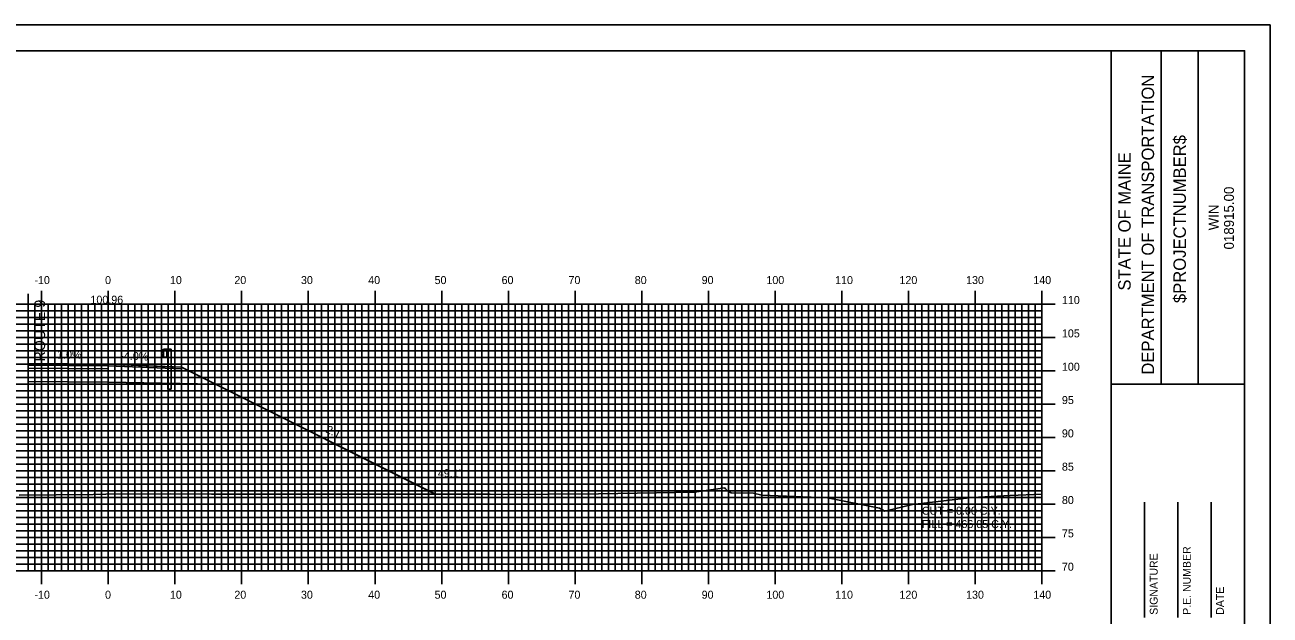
# Model space of a CAD drawing. Extents: x 2846 to 3190, y -1658 to -1438.
# Drawn here: x 2999.7 to 3186.4, y -1526.3 to -1437.7 of the extents above; entities that cross this region are included whole.
import ezdxf

# ---------------------------------------------------------------- set-up
doc = ezdxf.new("R2010")
doc.units = 0
for name, color, linetype in [('ANNOTATION', 7, 'Continuous'), ('BORDER', 7, 'Continuous'), ('D_Guardrail_Beam_Rt', 7, 'Continuous'), ('D_Roadway_Centerline', 7, 'Continuous'), ('D_Roadway_Centerline_Text', 7, 'Continuous'), ('D_Roadway_Edge_Shoulder', 7, 'Continuous'), ('D_Roadway_Edge_TW', 7, 'Continuous'), ('D_Roadway_Pavement', 7, 'Continuous'), ('D_Roadway_SlopeLines', 7, 'Continuous'), ('D_Roadway_SubGrade', 7, 'Continuous'), ('D_Text_Standard', 7, 'Continuous'), ('Default', 7, 'Continuous'), ('H_V ANNOTATION', 7, 'Continuous'), ('MAJOR', 7, 'Continuous'), ('MINOR', 7, 'Continuous'), ('PLOT BOUNDARY', 7, 'Continuous'), ('S_Roadway_Centerline', 7, 'Continuous')]:
    doc.layers.add(name, color=color, linetype=linetype)

msp = doc.modelspace()

# ---------------------------------------------------------------- linework, layer by layer
at = {"layer": 'BORDER'}
for p, q in [((3162.61, -1651.6), (3162.61, -1441.6)), ((3170.07, -1491.61), (3170.07, -1441.61)), ((3175.66, -1491.61), (3175.66, -1441.61)), ((3162.61, -1491.62), (3182.61, -1491.62)), ((3167.61, -1526.6), (3167.61, -1509.3)), ((3172.61, -1526.6), (3172.61, -1509.3)), ((3177.61, -1526.6), (3177.61, -1509.3))]:
    msp.add_line(p, q, dxfattribs=at)
msp.add_lwpolyline([(2862.61, -1651.6), (3182.61, -1651.6), (3182.61, -1441.6), (2862.61, -1441.6)], close=True, dxfattribs=at)
at = {"layer": 'D_Guardrail_Beam_Rt'}
for p, q in [((3020.39, -1486.49), (3020.25, -1486.59)), ((3020.25, -1486.73), (3020.45, -1486.87)), ((3020.45, -1487.06), (3020.25, -1487.2)), ((3020.25, -1487.34), (3020.39, -1487.44)), ((3020.48, -1486.46), (3020.41, -1486.48)), ((3020.41, -1487.45), (3020.48, -1487.46)), ((3020.48, -1486.38), (3021.17, -1486.38)), ((3020.48, -1487.55), (3020.48, -1486.38)), ((3020.48, -1486.93), (3020.48, -1487)), ((3021.17, -1487.55), (3020.48, -1487.55)), ((3021, -1486.38), (3021, -1487.55)), ((3021.11, -1486.38), (3021.11, -1487.55)), ((3021.15, -1492.38), (3021.15, -1487.55)), ((3021.17, -1486.38), (3021.64, -1486.38)), ((3021.17, -1486.38), (3021.17, -1487.55)), ((3021.64, -1486.38), (3021.64, -1492.38)), ((3021.15, -1492.38), (3021.64, -1492.38))]:
    msp.add_line(p, q, dxfattribs=at)
for centre, major_axis, start_param, end_param in [((3020.3, -1486.66), (-0.0877, 0), 5.323254, 7.243116), ((3020.3, -1487.27), (-0.0877, 0), 5.323254, 7.243116), ((3020.42, -1486.52), (-0.0417, 0), 4.907132, 5.323254), ((3020.42, -1487.41), (-0.0417, 0), 0.959931, 1.376053), ((3020.4, -1486.93), (0.0789, 0), 0, 0.959931), ((3020.4, -1487), (0.0789, 0), 5.323254, 6.283185)]:
    msp.add_ellipse(centre, major_axis=major_axis, ratio=0.995501, start_param=start_param, end_param=end_param, dxfattribs=at)
at = {"layer": 'D_Roadway_Centerline'}
msp.add_lwpolyline([(3000.21, -1488.53), (3012.2, -1488.64), (3012.21, -1488.64), (3020.21, -1488.96), (3020.21, -1488.96), (3023.21, -1489.08), (3023.21, -1489.08), (3028.31, -1491.63), (3028.31, -1491.63), (3061.25, -1508.1), (3061.28, -1508.12)], dxfattribs=at)
at = {"layer": 'D_Roadway_Edge_Shoulder'}
for points in [[(3012.21, -1488.64), (3023.21, -1489.08), (3023.21, -1489.33), (3012.21, -1488.89)], [(3012.21, -1488.64), (3020.21, -1488.96), (3020.21, -1488.96), (3023.21, -1489.08), (3023.21, -1489.33), (3012.21, -1488.89)], [(3012.21, -1488.64), (3020.21, -1488.96), (3020.21, -1488.96), (3023.21, -1489.08), (3023.21, -1489.33), (3012.21, -1488.89)], [(3012.21, -1488.64), (3023.21, -1489.08), (3023.21, -1489.33), (3012.21, -1488.89)], [(3012.21, -1488.64), (3023.21, -1489.08), (3023.21, -1489.33), (3012.21, -1488.89)]]:
    msp.add_lwpolyline(points, close=True, dxfattribs=at)
at = {"layer": 'D_Roadway_Edge_TW'}
msp.add_lwpolyline([(3000.21, -1488.53), (3000.21, -1488.78)], dxfattribs=at)
msp.add_lwpolyline([(3000.21, -1488.53), (3000.21, -1488.78)], dxfattribs=at)
msp.add_lwpolyline([(3000.21, -1488.53), (3012.21, -1488.64), (3012.21, -1488.89), (3000.21, -1488.78)], close=True, dxfattribs=at)
msp.add_lwpolyline([(3000.21, -1488.53), (3012.21, -1488.64), (3012.21, -1488.89), (3000.21, -1488.78)], close=True, dxfattribs=at)
msp.add_lwpolyline([(3000.21, -1488.53), (3012.21, -1488.64), (3012.21, -1488.89), (3000.21, -1488.78)], close=True, dxfattribs=at)
at = {"layer": 'D_Roadway_Pavement'}
for points in [[(3000.21, -1488.78), (3000.21, -1489.2)], [(3000.21, -1488.78), (3000.21, -1489.2)], [(3000.21, -1488.78), (3000.21, -1489.2)], [(3000.21, -1488.78), (3000.21, -1489.2)], [(3012.21, -1488.89), (3012.21, -1489.31)], [(3012.21, -1488.89), (3012.21, -1489.31)], [(3012.21, -1488.89), (3012.21, -1489.31)], [(3012.21, -1488.89), (3012.21, -1489.31)], [(3012.21, -1488.89), (3012.21, -1489.31)], [(3012.21, -1488.89), (3012.21, -1489.31)], [(3012.21, -1488.89), (3012.21, -1489.31)], [(3012.21, -1488.89), (3012.21, -1489.31)], [(3012.21, -1488.89), (3012.21, -1489.31)], [(3012.21, -1488.89), (3012.21, -1489.31)], [(3012.21, -1488.89), (3012.21, -1489.31)], [(3012.21, -1488.89), (3012.21, -1489.31)], [(3012.21, -1488.89), (3012.21, -1489.31)], [(3012.21, -1488.89), (3012.21, -1489.31)]]:
    msp.add_lwpolyline(points, dxfattribs=at)
msp.add_lwpolyline([(3000.21, -1488.78), (3012.21, -1488.89), (3012.21, -1489.31), (3000.21, -1489.2)], close=True, dxfattribs=at)
msp.add_lwpolyline([(3000.21, -1488.78), (3012.21, -1488.89), (3012.21, -1489.31), (3000.21, -1489.2)], close=True, dxfattribs=at)
msp.add_lwpolyline([(3000.21, -1488.78), (3012.21, -1488.89), (3012.21, -1489.31), (3000.21, -1489.2)], close=True, dxfattribs=at)
at = {"layer": 'D_Roadway_SlopeLines'}
msp.add_lwpolyline([(3023.21, -1489.08), (3061.28, -1508.12)], dxfattribs=at)
msp.add_lwpolyline([(3023.21, -1489.08), (3061.28, -1508.12)], dxfattribs=at)
msp.add_lwpolyline([(3023.21, -1489.08), (3061.28, -1508.12)], dxfattribs=at)
msp.add_lwpolyline([(3023.21, -1489.08), (3061.28, -1508.12)], dxfattribs=at)
at = {"layer": 'D_Roadway_SubGrade'}
msp.add_line((3000.21, -1478.06), (3000.21, -1491.2), dxfattribs=at)
for points in [[(3000.21, -1489.2), (3012.21, -1489.31), (3012.21, -1491.31), (3000.21, -1491.2)], [(3000.21, -1489.2), (3012.21, -1489.31), (3012.21, -1491.31), (3000.21, -1491.2)], [(3000.21, -1489.2), (3012.21, -1489.31), (3012.21, -1491.31), (3000.21, -1491.2)], [(3012.21, -1489.31), (3012.21, -1488.89), (3023.21, -1489.33), (3023.21, -1489.08), (3028.31, -1491.63), (3012.21, -1491.31)], [(3012.21, -1489.31), (3012.21, -1488.89), (3023.21, -1489.33), (3023.21, -1489.08), (3028.31, -1491.63), (3012.21, -1491.31)], [(3012.21, -1489.31), (3012.21, -1488.89), (3023.21, -1489.33), (3023.21, -1489.08), (3028.31, -1491.63), (3012.21, -1491.31)], [(3012.21, -1489.31), (3012.21, -1488.89), (3023.21, -1489.33), (3023.21, -1489.08), (3028.31, -1491.63), (3012.21, -1491.31)]]:
    msp.add_lwpolyline(points, close=True, dxfattribs=at)
for points in [[(3000.21, -1489.2), (3000.21, -1491.2)], [(3000.21, -1489.2), (3000.21, -1491.2)], [(3028.31, -1491.63), (3012.21, -1491.31), (3012.21, -1489.31), (3012.21, -1488.89), (3023.21, -1489.33)]]:
    msp.add_lwpolyline(points, dxfattribs=at)
at = {"layer": 'Default'}
msp.add_line((3000.21, -1491.2), (3000.21, -1486.87), dxfattribs=at)
at = {"layer": 'MAJOR'}
for p, q in [((3002.21, -1477.6), (3002.21, -1479.6)), ((3012.21, -1477.6), (3012.21, -1479.6)), ((3022.21, -1477.6), (3022.21, -1479.6)), ((3032.21, -1477.6), (3032.21, -1479.6)), ((3042.21, -1477.6), (3042.21, -1479.6)), ((3052.21, -1477.6), (3052.21, -1479.6)), ((3062.21, -1477.6), (3062.21, -1479.6)), ((3072.21, -1477.6), (3072.21, -1479.6)), ((3082.21, -1477.6), (3082.21, -1479.6)), ((3092.21, -1477.6), (3092.21, -1479.6)), ((3102.21, -1477.6), (3102.21, -1479.6)), ((3112.21, -1477.6), (3112.21, -1479.6)), ((3122.21, -1477.6), (3122.21, -1479.6)), ((3132.21, -1477.6), (3132.21, -1479.6)), ((3142.21, -1477.6), (3142.21, -1479.6)), ((3152.21, -1477.6), (3152.21, -1479.6)), ((2872.21, -1479.6), (3152.21, -1479.6)), ((2872.21, -1479.6), (3152.21, -1479.6)), ((3002.21, -1519.6), (3002.21, -1479.6)), ((3012.21, -1519.6), (3012.21, -1479.6)), ((3022.21, -1519.6), (3022.21, -1479.6)), ((3032.21, -1519.6), (3032.21, -1479.6)), ((3042.21, -1519.6), (3042.21, -1479.6)), ((3052.21, -1519.6), (3052.21, -1479.6)), ((3062.21, -1519.6), (3062.21, -1479.6)), ((3072.21, -1519.6), (3072.21, -1479.6)), ((3082.21, -1519.6), (3082.21, -1479.6)), ((3092.21, -1519.6), (3092.21, -1479.6)), ((3102.21, -1519.6), (3102.21, -1479.6)), ((3112.21, -1519.6), (3112.21, -1479.6)), ((3122.21, -1519.6), (3122.21, -1479.6)), ((3132.21, -1519.6), (3132.21, -1479.6)), ((3142.21, -1519.6), (3142.21, -1479.6)), ((3154.22, -1479.6), (3150.21, -1479.6)), ((3152.21, -1519.6), (3152.21, -1479.6)), ((3152.21, -1519.6), (3152.21, -1479.6)), ((2872.21, -1484.6), (3152.21, -1484.6)), ((3154.22, -1484.6), (3150.21, -1484.6)), ((2872.21, -1489.6), (3152.21, -1489.6)), ((3154.22, -1489.6), (3150.21, -1489.6)), ((2872.21, -1494.6), (3152.21, -1494.6)), ((3154.22, -1494.6), (3150.21, -1494.6)), ((2872.21, -1499.6), (3152.21, -1499.6)), ((3154.22, -1499.6), (3150.21, -1499.6)), ((2872.21, -1504.6), (3152.21, -1504.6)), ((3154.22, -1504.6), (3150.21, -1504.6)), ((2872.21, -1509.6), (3152.21, -1509.6)), ((3154.22, -1509.6), (3150.21, -1509.6)), ((2872.21, -1514.6), (3152.21, -1514.6)), ((3154.22, -1514.6), (3150.21, -1514.6)), ((2872.21, -1519.6), (3152.21, -1519.6)), ((2872.21, -1519.6), (3152.21, -1519.6)), ((3002.21, -1521.61), (3002.21, -1519.6)), ((3012.21, -1521.61), (3012.21, -1519.6)), ((3022.21, -1521.61), (3022.21, -1519.6)), ((3032.21, -1521.61), (3032.21, -1519.6)), ((3042.21, -1521.61), (3042.21, -1519.6)), ((3052.21, -1521.61), (3052.21, -1519.6)), ((3062.21, -1521.61), (3062.21, -1519.6)), ((3072.21, -1521.61), (3072.21, -1519.6)), ((3082.21, -1521.61), (3082.21, -1519.6)), ((3092.21, -1521.61), (3092.21, -1519.6)), ((3102.21, -1521.61), (3102.21, -1519.6)), ((3112.21, -1521.61), (3112.21, -1519.6)), ((3122.21, -1521.61), (3122.21, -1519.6)), ((3132.21, -1521.61), (3132.21, -1519.6)), ((3142.21, -1521.61), (3142.21, -1519.6)), ((3154.22, -1519.6), (3150.21, -1519.6)), ((3152.21, -1521.61), (3152.21, -1519.6))]:
    msp.add_line(p, q, dxfattribs=at)
at = {"layer": 'MINOR'}
for p, q in [((2872.21, -1480.6), (3152.21, -1480.6)), ((3000.21, -1519.6), (3000.21, -1479.6)), ((3001.21, -1519.6), (3001.21, -1479.6)), ((3003.21, -1519.6), (3003.21, -1479.6)), ((3004.21, -1519.6), (3004.21, -1479.6)), ((3005.21, -1519.6), (3005.21, -1479.6)), ((3006.21, -1519.6), (3006.21, -1479.6)), ((3007.21, -1519.6), (3007.21, -1479.6)), ((3008.21, -1519.6), (3008.21, -1479.6)), ((3009.21, -1519.6), (3009.21, -1479.6)), ((3010.21, -1519.6), (3010.21, -1479.6)), ((3011.21, -1519.6), (3011.21, -1479.6)), ((3013.21, -1519.6), (3013.21, -1479.6)), ((3014.21, -1519.6), (3014.21, -1479.6)), ((3015.21, -1519.6), (3015.21, -1479.6)), ((3016.21, -1519.6), (3016.21, -1479.6)), ((3017.21, -1519.6), (3017.21, -1479.6)), ((3018.21, -1519.6), (3018.21, -1479.6)), ((3019.21, -1519.6), (3019.21, -1479.6)), ((3020.21, -1519.6), (3020.21, -1479.6)), ((3021.21, -1519.6), (3021.21, -1479.6)), ((3023.21, -1519.6), (3023.21, -1479.6)), ((3024.21, -1519.6), (3024.21, -1479.6)), ((3025.21, -1519.6), (3025.21, -1479.6)), ((3026.21, -1519.6), (3026.21, -1479.6)), ((3027.21, -1519.6), (3027.21, -1479.6)), ((3028.21, -1519.6), (3028.21, -1479.6)), ((3029.21, -1519.6), (3029.21, -1479.6)), ((3030.21, -1519.6), (3030.21, -1479.6)), ((3031.21, -1519.6), (3031.21, -1479.6)), ((3033.21, -1519.6), (3033.21, -1479.6)), ((3034.21, -1519.6), (3034.21, -1479.6)), ((3035.21, -1519.6), (3035.21, -1479.6)), ((3036.21, -1519.6), (3036.21, -1479.6)), ((3037.21, -1519.6), (3037.21, -1479.6)), ((3038.21, -1519.6), (3038.21, -1479.6)), ((3039.21, -1519.6), (3039.21, -1479.6)), ((3040.21, -1519.6), (3040.21, -1479.6)), ((3041.21, -1519.6), (3041.21, -1479.6)), ((3043.21, -1519.6), (3043.21, -1479.6)), ((3044.21, -1519.6), (3044.21, -1479.6)), ((3045.21, -1519.6), (3045.21, -1479.6)), ((3046.21, -1519.6), (3046.21, -1479.6)), ((3047.21, -1519.6), (3047.21, -1479.6)), ((3048.21, -1519.6), (3048.21, -1479.6)), ((3049.21, -1519.6), (3049.21, -1479.6)), ((3050.21, -1519.6), (3050.21, -1479.6)), ((3051.21, -1519.6), (3051.21, -1479.6)), ((3053.21, -1519.6), (3053.21, -1479.6)), ((3054.21, -1519.6), (3054.21, -1479.6)), ((3055.21, -1519.6), (3055.21, -1479.6)), ((3056.21, -1519.6), (3056.21, -1479.6)), ((3057.21, -1519.6), (3057.21, -1479.6)), ((3058.21, -1519.6), (3058.21, -1479.6)), ((3059.21, -1519.6), (3059.21, -1479.6)), ((3060.21, -1519.6), (3060.21, -1479.6)), ((3061.21, -1519.6), (3061.21, -1479.6)), ((3063.21, -1519.6), (3063.21, -1479.6)), ((3064.21, -1519.6), (3064.21, -1479.6)), ((3065.21, -1519.6), (3065.21, -1479.6)), ((3066.21, -1519.6), (3066.21, -1479.6)), ((3067.21, -1519.6), (3067.21, -1479.6)), ((3068.21, -1519.6), (3068.21, -1479.6)), ((3069.21, -1519.6), (3069.21, -1479.6)), ((3070.21, -1519.6), (3070.21, -1479.6)), ((3071.21, -1519.6), (3071.21, -1479.6)), ((3073.21, -1519.6), (3073.21, -1479.6)), ((3074.21, -1519.6), (3074.21, -1479.6)), ((3075.21, -1519.6), (3075.21, -1479.6)), ((3076.21, -1519.6), (3076.21, -1479.6)), ((3077.21, -1519.6), (3077.21, -1479.6)), ((3078.21, -1519.6), (3078.21, -1479.6)), ((3079.21, -1519.6), (3079.21, -1479.6)), ((3080.21, -1519.6), (3080.21, -1479.6)), ((3081.21, -1519.6), (3081.21, -1479.6)), ((3083.21, -1519.6), (3083.21, -1479.6)), ((3084.21, -1519.6), (3084.21, -1479.6)), ((3085.21, -1519.6), (3085.21, -1479.6)), ((3086.21, -1519.6), (3086.21, -1479.6)), ((3087.21, -1519.6), (3087.21, -1479.6)), ((3088.21, -1519.6), (3088.21, -1479.6)), ((3089.21, -1519.6), (3089.21, -1479.6)), ((3090.21, -1519.6), (3090.21, -1479.6)), ((3091.21, -1519.6), (3091.21, -1479.6)), ((3093.21, -1519.6), (3093.21, -1479.6)), ((3094.21, -1519.6), (3094.21, -1479.6)), ((3095.21, -1519.6), (3095.21, -1479.6)), ((3096.21, -1519.6), (3096.21, -1479.6)), ((3097.21, -1519.6), (3097.21, -1479.6)), ((3098.21, -1519.6), (3098.21, -1479.6)), ((3099.21, -1519.6), (3099.21, -1479.6)), ((3100.21, -1519.6), (3100.21, -1479.6)), ((3101.21, -1519.6), (3101.21, -1479.6)), ((3103.21, -1519.6), (3103.21, -1479.6)), ((3104.21, -1519.6), (3104.21, -1479.6)), ((3105.21, -1519.6), (3105.21, -1479.6)), ((3106.21, -1519.6), (3106.21, -1479.6)), ((3107.21, -1519.6), (3107.21, -1479.6)), ((3108.21, -1519.6), (3108.21, -1479.6)), ((3109.21, -1519.6), (3109.21, -1479.6)), ((3110.21, -1519.6), (3110.21, -1479.6)), ((3111.21, -1519.6), (3111.21, -1479.6)), ((3113.21, -1519.6), (3113.21, -1479.6)), ((3114.21, -1519.6), (3114.21, -1479.6)), ((3115.21, -1519.6), (3115.21, -1479.6)), ((3116.21, -1519.6), (3116.21, -1479.6)), ((3117.21, -1519.6), (3117.21, -1479.6)), ((3118.21, -1519.6), (3118.21, -1479.6)), ((3119.21, -1519.6), (3119.21, -1479.6)), ((3120.21, -1519.6), (3120.21, -1479.6)), ((3121.21, -1519.6), (3121.21, -1479.6)), ((3123.21, -1519.6), (3123.21, -1479.6)), ((3124.21, -1519.6), (3124.21, -1479.6)), ((3125.21, -1519.6), (3125.21, -1479.6)), ((3126.21, -1519.6), (3126.21, -1479.6)), ((3127.21, -1519.6), (3127.21, -1479.6)), ((3128.21, -1519.6), (3128.21, -1479.6)), ((3129.21, -1519.6), (3129.21, -1479.6)), ((3130.21, -1519.6), (3130.21, -1479.6)), ((3131.21, -1519.6), (3131.21, -1479.6)), ((3133.21, -1519.6), (3133.21, -1479.6)), ((3134.21, -1519.6), (3134.21, -1479.6)), ((3135.21, -1519.6), (3135.21, -1479.6)), ((3136.21, -1519.6), (3136.21, -1479.6)), ((3137.21, -1519.6), (3137.21, -1479.6)), ((3138.21, -1519.6), (3138.21, -1479.6)), ((3139.21, -1519.6), (3139.21, -1479.6)), ((3140.21, -1519.6), (3140.21, -1479.6)), ((3141.21, -1519.6), (3141.21, -1479.6)), ((3143.21, -1519.6), (3143.21, -1479.6)), ((3144.21, -1519.6), (3144.21, -1479.6)), ((3145.21, -1519.6), (3145.21, -1479.6)), ((3146.21, -1519.6), (3146.21, -1479.6)), ((3147.21, -1519.6), (3147.21, -1479.6)), ((3148.21, -1519.6), (3148.21, -1479.6)), ((3149.21, -1519.6), (3149.21, -1479.6)), ((3150.21, -1519.6), (3150.21, -1479.6)), ((3152.21, -1480.6), (3150.21, -1480.6)), ((3151.21, -1519.6), (3151.21, -1479.6)), ((2872.21, -1481.6), (3152.21, -1481.6)), ((3152.21, -1481.6), (3150.21, -1481.6)), ((2872.21, -1482.6), (3152.21, -1482.6)), ((2872.21, -1483.6), (3152.21, -1483.6)), ((3152.21, -1482.6), (3150.21, -1482.6)), ((3152.21, -1483.6), (3150.21, -1483.6)), ((2872.21, -1485.6), (3152.21, -1485.6)), ((3152.21, -1485.6), (3150.21, -1485.6)), ((2872.21, -1486.6), (3152.21, -1486.6)), ((2872.21, -1487.6), (3152.21, -1487.6)), ((3152.21, -1486.6), (3150.21, -1486.6)), ((3152.21, -1487.6), (3150.21, -1487.6)), ((2872.21, -1488.6), (3152.21, -1488.6)), ((3152.21, -1488.6), (3150.21, -1488.6)), ((2872.21, -1490.6), (3152.21, -1490.6)), ((2872.21, -1491.6), (3152.21, -1491.6)), ((3152.21, -1490.6), (3150.21, -1490.6)), ((3152.21, -1491.6), (3150.21, -1491.6)), ((2872.21, -1492.6), (3152.21, -1492.6)), ((2872.21, -1493.6), (3152.21, -1493.6)), ((3152.21, -1492.6), (3150.21, -1492.6)), ((3152.21, -1493.6), (3150.21, -1493.6)), ((2872.21, -1495.6), (3152.21, -1495.6)), ((2872.21, -1496.6), (3152.21, -1496.6)), ((3152.21, -1495.6), (3150.21, -1495.6)), ((3152.21, -1496.6), (3150.21, -1496.6)), ((2872.21, -1497.6), (3152.21, -1497.6)), ((2872.21, -1498.6), (3152.21, -1498.6)), ((3152.21, -1497.6), (3150.21, -1497.6)), ((3152.21, -1498.6), (3150.21, -1498.6)), ((2872.21, -1500.6), (3152.21, -1500.6)), ((3152.21, -1500.6), (3150.21, -1500.6)), ((2872.21, -1501.6), (3152.21, -1501.6)), ((2872.21, -1502.6), (3152.21, -1502.6)), ((3152.21, -1501.6), (3150.21, -1501.6)), ((3152.21, -1502.6), (3150.21, -1502.6)), ((2872.21, -1503.6), (3152.21, -1503.6)), ((3152.21, -1503.6), (3150.21, -1503.6)), ((2872.21, -1505.6), (3152.21, -1505.6)), ((2872.21, -1506.6), (3152.21, -1506.6)), ((3152.21, -1505.6), (3150.21, -1505.6)), ((3152.21, -1506.6), (3150.21, -1506.6)), ((2872.21, -1507.6), (3152.21, -1507.6)), ((2872.21, -1508.6), (3152.21, -1508.6)), ((3152.21, -1507.6), (3150.21, -1507.6)), ((3152.21, -1508.6), (3150.21, -1508.6)), ((2872.21, -1510.6), (3152.21, -1510.6)), ((2872.21, -1511.6), (3152.21, -1511.6)), ((3152.21, -1510.6), (3150.21, -1510.6)), ((3152.21, -1511.6), (3150.21, -1511.6)), ((2872.21, -1512.6), (3152.21, -1512.6)), ((2872.21, -1513.6), (3152.21, -1513.6)), ((3152.21, -1512.6), (3150.21, -1512.6)), ((3152.21, -1513.6), (3150.21, -1513.6)), ((2872.21, -1515.6), (3152.21, -1515.6)), ((3152.21, -1515.6), (3150.21, -1515.6)), ((2872.21, -1516.6), (3152.21, -1516.6)), ((2872.21, -1517.6), (3152.21, -1517.6)), ((3152.21, -1516.6), (3150.21, -1516.6)), ((3152.21, -1517.6), (3150.21, -1517.6)), ((2872.21, -1518.6), (3152.21, -1518.6)), ((3152.21, -1518.6), (3150.21, -1518.6))]:
    msp.add_line(p, q, dxfattribs=at)
at = {"layer": 'PLOT BOUNDARY'}
msp.add_lwpolyline([(2846.43, -1657.72), (3186.43, -1657.72), (3186.43, -1437.72), (2846.43, -1437.72)], close=True, dxfattribs=at)
at = {"layer": 'S_Roadway_Centerline'}
msp.add_lwpolyline([(2998.86, -1508.25), (3009.93, -1508.16), (3011.86, -1508.14), (3021.5, -1508.07), (3027.69, -1508.1), (3044.2, -1508.12), (3057.77, -1508.11), (3069.49, -1508.13), (3071.48, -1508.18), (3078.22, -1508.14), (3085.72, -1508.06), (3097.32, -1507.87), (3100.18, -1507.82), (3100.82, -1507.74), (3104.65, -1507.16), (3104.79, -1507.3), (3105.23, -1507.73), (3105.64, -1507.9), (3108.98, -1507.99), (3110.2, -1508.27), (3120.04, -1508.69), (3127.87, -1510.21), (3128.65, -1510.68), (3132.8, -1509.69), (3141.77, -1508.64), (3147.43, -1508.34), (3152.21, -1508.11)], dxfattribs=at)

# ---------------------------------------------------------------- texts
at = {"layer": 'ANNOTATION'}
for s, height, rotation, p in [('ROUTE 9', 1.6, 90, (3002.74, -1488.22)), ('1.0%', 1.2, 359.4458, (3004.54, -1487.77)), ('-4.0%', 1.2, 357.7095, (3014, -1487.91)), ('2:1', 1.2, 333.435, (3044.72, -1498.8))]:
    msp.add_text(s, height=height, rotation=rotation, dxfattribs=at).set_placement(p)
at = {"layer": 'BORDER'}
for s, height, p in [('DEPARTMENT OF TRANSPORTATION', 1.8635, (3169.03, -1490.19)), ('$PROJECTNUMBER$', 1.8635, (3173.8, -1479.45)), ('STATE OF MAINE', 1.8635, (3165.52, -1477.58)), ('018915.00', 1.491, (3181, -1471.41)), ('WIN', 1.491, (3178.69, -1468.54)), ('P.E. NUMBER', 1.1811, (3174.53, -1526.21)), ('SIGNATURE', 1.181, (3169.57, -1526.21)), ('DATE', 1.181, (3179.5, -1526.21))]:
    msp.add_text(s, height=height, rotation=90, dxfattribs=at).set_placement(p)
at = {"layer": 'D_Roadway_Centerline_Text'}
msp.add_text('100.96', height=1.2, dxfattribs=at).set_placement((3009.54, -1479.55))
at = {"layer": 'D_Text_Standard'}
for s, p in [("49.1'", (3061.64, -1505.57)), ('CUT = 0.00 C.Y.', (3134.21, -1511.2)), ('FILL = 466.05 C.Y.', (3134.21, -1513.2))]:
    msp.add_text(s, height=1.2, dxfattribs=at).set_placement(p)
at = {"layer": 'H_V ANNOTATION'}
for s, p in [('-10', (3001.14, -1476.6)), ('0', (3011.73, -1476.6)), ('10', (3021.46, -1476.6)), ('20', (3031.12, -1476.6)), ('30', (3041.11, -1476.6)), ('40', (3051.19, -1476.6)), ('50', (3061.14, -1476.6)), ('60', (3071.19, -1476.6)), ('70', (3081.22, -1476.6)), ('80', (3091.16, -1476.6)), ('90', (3101.19, -1476.6)), ('100', (3110.9, -1476.6)), ('110', (3121.2, -1476.6)), ('120', (3130.85, -1476.6)), ('130', (3140.84, -1476.6)), ('140', (3150.92, -1476.6)), ('110', (3155.21, -1479.6)), ('105', (3155.21, -1484.6)), ('100', (3155.21, -1489.6)), ('95', (3155.21, -1494.6)), ('90', (3155.21, -1499.6)), ('85', (3155.21, -1504.6)), ('80', (3155.21, -1509.6)), ('75', (3155.21, -1514.6)), ('70', (3155.21, -1519.6)), ('-10', (3001.14, -1523.8)), ('0', (3011.73, -1523.8)), ('10', (3021.46, -1523.8)), ('20', (3031.12, -1523.8)), ('30', (3041.11, -1523.8)), ('40', (3051.19, -1523.8)), ('50', (3061.14, -1523.8)), ('60', (3071.19, -1523.8)), ('70', (3081.22, -1523.8)), ('80', (3091.16, -1523.8)), ('90', (3101.19, -1523.8)), ('100', (3110.9, -1523.8)), ('110', (3121.2, -1523.8)), ('120', (3130.85, -1523.8)), ('130', (3140.84, -1523.8)), ('140', (3150.92, -1523.8))]:
    msp.add_text(s, height=1.2, dxfattribs=at).set_placement(p)

doc.saveas('drawing.dxf')
